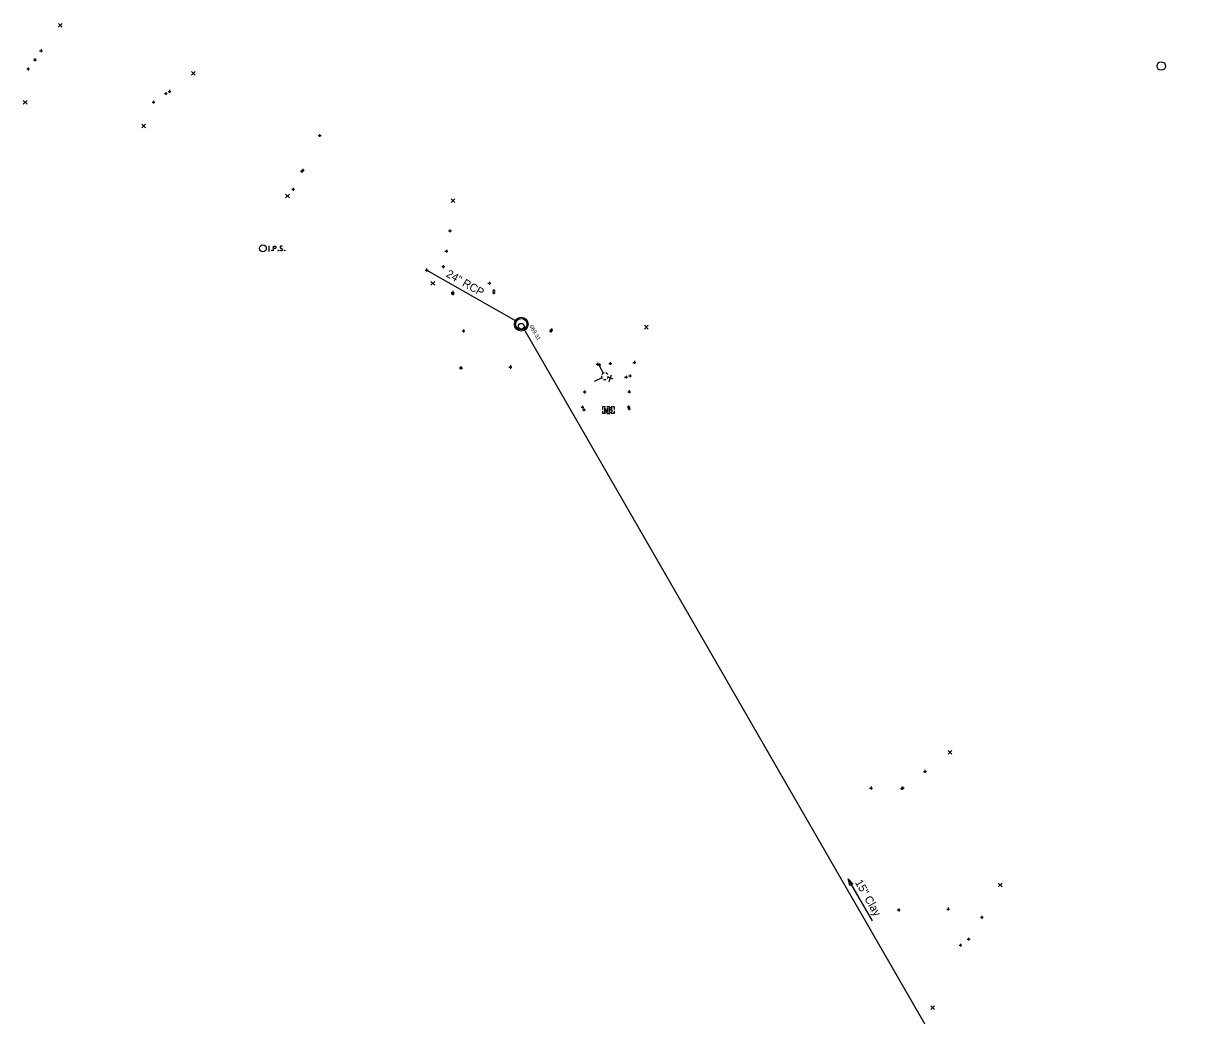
# Model space of a CAD drawing. Extents: x 2188719 to 2189819, y 654569 to 659504.
# Drawn here: x 2189134.5 to 2189542.6, y 658968.9 to 659316 of the extents above; entities that cross this region are included whole.
import ezdxf

# ---------------------------------------------------------------- set-up
doc = ezdxf.new("R2010")
doc.units = 0
for name, color, linetype in [('DR_X_Cells', 7, 'Continuous'), ('DR_X_Elev_Flow', 7, 'Continuous'), ('DR_X_Storm_Sewer', 7, 'Continuous'), ('DR_X_Text', 7, 'Continuous'), ('GK_Drainage_Nodes', 7, 'Continuous'), ('RD_X_Cells', 7, 'Continuous'), ('SC_Scratch1', 7, 'Continuous'), ('SV_P_Mon_Cells_Set', 7, 'Continuous'), ('SV_X_Random_Point', 7, 'Continuous'), ('SV_X_Shot_Marker', 7, 'Continuous'), ('UT_X_Water_Cells', 7, 'Continuous')]:
    doc.layers.add(name, color=color, linetype=linetype)

msp = doc.modelspace()

# ---------------------------------------------------------------- linework, layer by layer
at = {"layer": 'DR_X_Cells'}
for centre, radius in [((2189308.74, 659210.8), 2.42), ((2189308.74, 659210.8), 2), ((2189308.74, 659210.05), 1)]:
    msp.add_circle(centre, radius, dxfattribs=at)
at = {"layer": 'DR_X_Elev_Flow'}
for p, q in [((2189275.13, 659229.7), (2189276.13, 659229.7)), ((2189275.63, 659230.2), (2189275.63, 659229.2)), ((2189275.63, 659229.7), (2189275.63, 659229.7))]:
    msp.add_line(p, q, dxfattribs=at)
at = {"layer": 'DR_X_Storm_Sewer'}
for p, q in [((2189306.96, 659211.82), (2189275.63, 659229.7)), ((2189542.62, 658805.63), (2189309.74, 659209.07))]:
    msp.add_line(p, q, dxfattribs=at)
at = {"layer": 'DR_X_Text'}
msp.add_line((2189431.6, 659002.02), (2189423.08, 659016.79), dxfattribs=at)
msp.add_lwpolyline([(2189423.08, 659016.79), (2189424.8, 659015.01), (2189423.76, 659014.41)], close=True, dxfattribs=at)
at = {"layer": 'GK_Drainage_Nodes'}
for p, q in [((2189308.74, 659212.8), (2189308.74, 659212.8)), ((2189308.74, 659210.8), (2189308.74, 659210.8)), ((2189308.74, 659210.8), (2189308.74, 659210.8)), ((2189308.74, 659210.05), (2189308.74, 659210.05)), ((2189308.74, 659208.8), (2189308.74, 659208.8))]:
    msp.add_line(p, q, dxfattribs=at)
msp.add_circle((2189308.74, 659210.8), 2, dxfattribs=at)
at = {"layer": 'RD_X_Cells'}
for p, q in [((2189338.72, 659181.96), (2189339.72, 659181.96)), ((2189338.72, 659179.52), (2189339.72, 659179.52)), ((2189339.23, 659180.74), (2189339.23, 659180.74))]:
    msp.add_line(p, q, dxfattribs=at)
for points in [[(2189337.23, 659180.99), (2189337.23, 659181.96), (2189338.2, 659181.96)], [(2189338.2, 659179.52), (2189337.23, 659179.52), (2189337.23, 659180.49)], [(2189337.93, 659179.94), (2189337.93, 659181.54), (2189338.51, 659179.94), (2189339.07, 659181.54), (2189339.07, 659179.94)], [(2189340.25, 659180.81), (2189340.31, 659180.87), (2189340.35, 659180.91), (2189340.38, 659180.94), (2189340.39, 659180.97), (2189340.41, 659181.02), (2189340.43, 659181.06), (2189340.45, 659181.15), (2189340.45, 659181.18), (2189340.45, 659181.23), (2189340.44, 659181.31), (2189340.41, 659181.37), (2189340.38, 659181.42), (2189340.31, 659181.47), (2189340.26, 659181.5), (2189340.24, 659181.51), (2189340.17, 659181.54), (2189339.56, 659181.54), (2189339.56, 659179.94), (2189340.25, 659179.94), (2189340.34, 659179.99), (2189340.41, 659180.05), (2189340.48, 659180.15), (2189340.51, 659180.26), (2189340.53, 659180.38), (2189340.53, 659180.45), (2189340.5, 659180.53), (2189340.45, 659180.64), (2189340.39, 659180.72), (2189340.25, 659180.81), (2189339.56, 659180.81)], [(2189340.23, 659181.96), (2189341.23, 659181.96), (2189341.23, 659180.99)], [(2189341.23, 659180.49), (2189341.23, 659179.52), (2189340.23, 659179.52)]]:
    msp.add_lwpolyline(points, dxfattribs=at)
at = {"layer": 'SV_P_Mon_Cells_Set'}
for points in [[(2189220.34, 659238.08), (2189220.69, 659238.08)], [(2189220.34, 659236.48), (2189220.69, 659236.48)], [(2189220.51, 659236.48), (2189220.51, 659238.08)], [(2189221.47, 659236.69), (2189221.53, 659236.69), (2189221.56, 659236.67), (2189221.59, 659236.62), (2189221.59, 659236.55), (2189221.56, 659236.5), (2189221.53, 659236.48), (2189221.47, 659236.48), (2189221.44, 659236.5), (2189221.41, 659236.55), (2189221.41, 659236.62), (2189221.44, 659236.67), (2189221.47, 659236.69)], [(2189222.08, 659236.48), (2189222.08, 659238.08), (2189222.61, 659238.08), (2189222.66, 659238.06), (2189222.74, 659238.04), (2189222.77, 659238.01), (2189222.81, 659237.99), (2189222.85, 659237.93), (2189222.88, 659237.86), (2189222.91, 659237.76), (2189222.91, 659237.61), (2189222.89, 659237.56), (2189222.87, 659237.49), (2189222.83, 659237.4), (2189222.78, 659237.36), (2189222.75, 659237.33), (2189222.7, 659237.31), (2189222.61, 659237.3), (2189222.08, 659237.3)], [(2189223.72, 659236.69), (2189223.78, 659236.69), (2189223.81, 659236.67), (2189223.84, 659236.62), (2189223.84, 659236.55), (2189223.81, 659236.5), (2189223.78, 659236.48), (2189223.72, 659236.48), (2189223.69, 659236.5), (2189223.65, 659236.55), (2189223.65, 659236.62), (2189223.69, 659236.67), (2189223.72, 659236.69)], [(2189225.09, 659237.96), (2189225.07, 659237.99), (2189225.03, 659238.01), (2189224.93, 659238.05), (2189224.81, 659238.08), (2189224.72, 659238.08), (2189224.69, 659238.08), (2189224.55, 659238.04), (2189224.43, 659237.96), (2189224.35, 659237.86), (2189224.33, 659237.76), (2189224.33, 659237.69), (2189224.35, 659237.59), (2189224.44, 659237.5), (2189225.04, 659237.12), (2189225.1, 659237.07), (2189225.12, 659237.02), (2189225.14, 659236.94), (2189225.14, 659236.87), (2189225.13, 659236.79), (2189225.12, 659236.74), (2189225.1, 659236.68), (2189225.08, 659236.63), (2189225.05, 659236.59), (2189225.02, 659236.55), (2189224.99, 659236.53), (2189224.94, 659236.5), (2189224.91, 659236.49), (2189224.81, 659236.48), (2189224.66, 659236.48), (2189224.56, 659236.5), (2189224.42, 659236.59), (2189224.33, 659236.67)], [(2189225.9, 659236.69), (2189225.96, 659236.69), (2189225.99, 659236.67), (2189226.02, 659236.62), (2189226.02, 659236.55), (2189225.99, 659236.5), (2189225.96, 659236.48), (2189225.9, 659236.48), (2189225.87, 659236.5), (2189225.84, 659236.55), (2189225.84, 659236.62), (2189225.87, 659236.67), (2189225.9, 659236.69)]]:
    msp.add_lwpolyline(points, dxfattribs=at)
for centre, radius in [((2189532.7, 659301.08), 1.5), ((2189218.32, 659237.28), 1.2)]:
    msp.add_circle(centre, radius, dxfattribs=at)
at = {"layer": 'SV_X_Random_Point'}
for p, q in [((2189146.81, 659314.68), (2189148.14, 659316.01)), ((2189146.81, 659316.01), (2189148.14, 659314.68)), ((2189193.32, 659297.83), (2189194.65, 659299.16)), ((2189193.32, 659299.16), (2189194.65, 659297.83)), ((2189134.5, 659287.72), (2189135.84, 659289.05)), ((2189134.5, 659289.05), (2189135.84, 659287.72)), ((2189175.98, 659279.41), (2189177.31, 659280.74)), ((2189175.98, 659280.74), (2189177.31, 659279.41)), ((2189226.29, 659254.96), (2189227.62, 659256.3)), ((2189226.29, 659256.3), (2189227.62, 659254.96)), ((2189284.17, 659253.32), (2189285.5, 659254.66)), ((2189284.17, 659254.66), (2189285.5, 659253.32)), ((2189277.14, 659224.42), (2189278.47, 659225.76)), ((2189277.14, 659225.76), (2189278.47, 659224.42)), ((2189351.82, 659209.08), (2189353.15, 659210.41)), ((2189351.82, 659210.41), (2189353.15, 659209.08)), ((2189458.08, 659060.34), (2189459.41, 659061.68)), ((2189458.08, 659061.68), (2189459.41, 659060.34)), ((2189475.67, 659013.96), (2189477.01, 659015.3)), ((2189475.67, 659015.3), (2189477.01, 659013.96)), ((2189452.02, 658971.02), (2189453.36, 658972.35)), ((2189452.02, 658972.35), (2189453.36, 658971.02))]:
    msp.add_line(p, q, dxfattribs=at)
at = {"layer": 'SV_X_Shot_Marker'}
for p, q in [((2189140.21, 659306.44), (2189141.21, 659306.44)), ((2189140.71, 659306.94), (2189140.71, 659305.94)), ((2189140.71, 659306.44), (2189140.71, 659306.44)), ((2189138.07, 659303.28), (2189139.07, 659303.28)), ((2189138.57, 659303.78), (2189138.57, 659302.78)), ((2189138.57, 659303.28), (2189138.57, 659303.28)), ((2189135.68, 659300.07), (2189136.68, 659300.07)), ((2189136.18, 659300.57), (2189136.18, 659299.57)), ((2189136.18, 659300.07), (2189136.18, 659300.07)), ((2189183.86, 659291.49), (2189184.86, 659291.49)), ((2189184.36, 659291.99), (2189184.36, 659290.99)), ((2189184.36, 659291.49), (2189184.36, 659291.49)), ((2189185.15, 659292.21), (2189186.15, 659292.21)), ((2189185.65, 659292.71), (2189185.65, 659291.71)), ((2189185.65, 659292.21), (2189185.65, 659292.21)), ((2189179.55, 659288.45), (2189180.55, 659288.45)), ((2189180.05, 659288.95), (2189180.05, 659287.95)), ((2189180.05, 659288.45), (2189180.05, 659288.45)), ((2189237.67, 659276.78), (2189238.67, 659276.78)), ((2189238.17, 659277.28), (2189238.17, 659276.28)), ((2189238.17, 659276.78), (2189238.17, 659276.78)), ((2189231.83, 659264.65), (2189232.83, 659264.65)), ((2189231.98, 659264.75), (2189231.98, 659263.75)), ((2189232.33, 659265.15), (2189232.33, 659264.15)), ((2189232.33, 659264.65), (2189232.33, 659264.65)), ((2189231.48, 659264.25), (2189232.48, 659264.25)), ((2189231.98, 659264.25), (2189231.98, 659264.25)), ((2189228.42, 659257.95), (2189229.42, 659257.95)), ((2189228.92, 659258.45), (2189228.92, 659257.45)), ((2189228.92, 659257.95), (2189228.92, 659257.95)), ((2189283.28, 659243.43), (2189284.28, 659243.43)), ((2189283.78, 659243.93), (2189283.78, 659242.93)), ((2189283.78, 659243.43), (2189283.78, 659243.43)), ((2189282.04, 659236.31), (2189283.04, 659236.31)), ((2189282.54, 659236.81), (2189282.54, 659235.81)), ((2189282.54, 659236.31), (2189282.54, 659236.31)), ((2189280.94, 659230.9), (2189281.94, 659230.9)), ((2189281.44, 659231.4), (2189281.44, 659230.4)), ((2189281.44, 659230.9), (2189281.44, 659230.9)), ((2189297.08, 659225.07), (2189298.08, 659225.07)), ((2189297.58, 659225.57), (2189297.58, 659224.57)), ((2189297.58, 659225.07), (2189297.58, 659225.07)), ((2189284.25, 659221.9), (2189285.25, 659221.9)), ((2189284.25, 659221.45), (2189285.25, 659221.45)), ((2189284.75, 659222.4), (2189284.75, 659221.4)), ((2189284.75, 659221.95), (2189284.75, 659220.95)), ((2189284.75, 659221.9), (2189284.75, 659221.9)), ((2189284.75, 659221.45), (2189284.75, 659221.45)), ((2189298.64, 659221.79), (2189299.64, 659221.79)), ((2189298.66, 659222.48), (2189299.66, 659222.48)), ((2189299.14, 659222.29), (2189299.14, 659221.29)), ((2189299.14, 659221.79), (2189299.14, 659221.79)), ((2189299.16, 659222.98), (2189299.16, 659221.98)), ((2189299.16, 659222.48), (2189299.16, 659222.48)), ((2189288.02, 659208.42), (2189289.02, 659208.42)), ((2189288.52, 659208.92), (2189288.52, 659207.92)), ((2189288.52, 659208.42), (2189288.52, 659208.42)), ((2189309.58, 659209.44), (2189310.58, 659209.44)), ((2189310.08, 659209.94), (2189310.08, 659208.94)), ((2189310.08, 659209.44), (2189310.08, 659209.44)), ((2189318.61, 659208.35), (2189319.61, 659208.35)), ((2189318.77, 659208.8), (2189319.77, 659208.8)), ((2189319.11, 659208.85), (2189319.11, 659207.85)), ((2189319.11, 659208.35), (2189319.11, 659208.35)), ((2189319.27, 659209.3), (2189319.27, 659208.3)), ((2189319.27, 659208.8), (2189319.27, 659208.8)), ((2189287.11, 659195.63), (2189288.11, 659195.63)), ((2189287.12, 659195.41), (2189288.12, 659195.41)), ((2189287.61, 659196.13), (2189287.61, 659195.13)), ((2189287.61, 659195.63), (2189287.61, 659195.63)), ((2189287.62, 659195.91), (2189287.62, 659194.91)), ((2189287.62, 659195.41), (2189287.62, 659195.41)), ((2189304.44, 659195.69), (2189305.44, 659195.69)), ((2189304.45, 659195.89), (2189305.45, 659195.89)), ((2189304.94, 659196.19), (2189304.94, 659195.19)), ((2189304.94, 659195.69), (2189304.94, 659195.69)), ((2189304.95, 659196.39), (2189304.95, 659195.39)), ((2189304.95, 659195.89), (2189304.95, 659195.89)), ((2189334.94, 659196.8), (2189335.94, 659196.8)), ((2189335.44, 659197.3), (2189335.44, 659196.3)), ((2189335.44, 659196.8), (2189335.44, 659196.8)), ((2189335.57, 659196.58), (2189336.57, 659196.58)), ((2189336.07, 659197.08), (2189336.07, 659196.08)), ((2189336.07, 659196.58), (2189336.07, 659196.58)), ((2189339.39, 659197.04), (2189340.39, 659197.04)), ((2189339.89, 659197.54), (2189339.89, 659196.54)), ((2189339.89, 659197.04), (2189339.89, 659197.04)), ((2189347.82, 659197.41), (2189348.82, 659197.41)), ((2189348.32, 659197.91), (2189348.32, 659196.91)), ((2189348.32, 659197.41), (2189348.32, 659197.41)), ((2189344.89, 659192.26), (2189345.89, 659192.26)), ((2189345.39, 659192.76), (2189345.39, 659191.76)), ((2189345.39, 659192.26), (2189345.39, 659192.26)), ((2189346.31, 659192.69), (2189347.31, 659192.69)), ((2189346.31, 659192.69), (2189347.31, 659192.69)), ((2189346.81, 659193.19), (2189346.81, 659192.19)), ((2189346.81, 659193.19), (2189346.81, 659192.19)), ((2189346.81, 659192.69), (2189346.81, 659192.69)), ((2189346.81, 659192.69), (2189346.81, 659192.69)), ((2189330.4, 659187.06), (2189331.4, 659187.06)), ((2189330.9, 659187.56), (2189330.9, 659186.56)), ((2189330.9, 659187.06), (2189330.9, 659187.06)), ((2189346.05, 659187.17), (2189347.05, 659187.17)), ((2189346.55, 659187.67), (2189346.55, 659186.67)), ((2189346.55, 659187.17), (2189346.55, 659187.17)), ((2189329.67, 659181.73), (2189330.67, 659181.73)), ((2189330.16, 659180.81), (2189331.16, 659180.81)), ((2189330.17, 659182.23), (2189330.17, 659181.23)), ((2189330.17, 659181.73), (2189330.17, 659181.73)), ((2189330.66, 659181.31), (2189330.66, 659180.31)), ((2189330.66, 659180.81), (2189330.66, 659180.81)), ((2189345.8, 659181.88), (2189346.8, 659181.88)), ((2189346, 659181.17), (2189347, 659181.17)), ((2189346.3, 659182.38), (2189346.3, 659181.38)), ((2189346.3, 659181.88), (2189346.3, 659181.88)), ((2189346.5, 659181.67), (2189346.5, 659180.67)), ((2189346.5, 659181.17), (2189346.5, 659181.17)), ((2189449.5, 659054.34), (2189450.5, 659054.34)), ((2189450, 659054.84), (2189450, 659053.84)), ((2189450, 659054.34), (2189450, 659054.34)), ((2189430.62, 659048.51), (2189431.62, 659048.51)), ((2189431.12, 659049.01), (2189431.12, 659048.01)), ((2189431.12, 659048.51), (2189431.12, 659048.51)), ((2189441.42, 659048.41), (2189442.42, 659048.41)), ((2189441.62, 659048.47), (2189442.62, 659048.47)), ((2189441.68, 659048.56), (2189442.68, 659048.56)), ((2189441.92, 659048.91), (2189441.92, 659047.91)), ((2189441.92, 659048.41), (2189441.92, 659048.41)), ((2189442.12, 659048.97), (2189442.12, 659047.97)), ((2189442.12, 659048.47), (2189442.12, 659048.47)), ((2189442.18, 659049.06), (2189442.18, 659048.06)), ((2189442.18, 659048.56), (2189442.18, 659048.56)), ((2189440.31, 659005.89), (2189441.31, 659005.89)), ((2189440.81, 659006.39), (2189440.81, 659005.39)), ((2189440.81, 659005.89), (2189440.81, 659005.89)), ((2189457.6, 659006.18), (2189458.6, 659006.18)), ((2189457.62, 659006.14), (2189458.62, 659006.14)), ((2189458.1, 659006.68), (2189458.1, 659005.68)), ((2189458.1, 659006.18), (2189458.1, 659006.18)), ((2189458.12, 659006.64), (2189458.12, 659005.64)), ((2189458.12, 659006.14), (2189458.12, 659006.14)), ((2189469.4, 659003.32), (2189470.4, 659003.32)), ((2189469.9, 659003.82), (2189469.9, 659002.82)), ((2189469.9, 659003.32), (2189469.9, 659003.32)), ((2189464.77, 658995.68), (2189465.77, 658995.68)), ((2189465.27, 658996.18), (2189465.27, 658995.18)), ((2189465.27, 658995.68), (2189465.27, 658995.68)), ((2189461.94, 658993.57), (2189462.94, 658993.57)), ((2189462.44, 658994.07), (2189462.44, 658993.07)), ((2189462.44, 658993.57), (2189462.44, 658993.57))]:
    msp.add_line(p, q, dxfattribs=at)
at = {"layer": 'UT_X_Water_Cells'}
for p, q in [((2189337.44, 659193.65), (2189336.14, 659196.28)), ((2189336.9, 659192.05), (2189334.27, 659190.74)), ((2189337.98, 659192.58), (2189337.98, 659192.58)), ((2189337.98, 659192.58), (2189337.98, 659192.58)), ((2189339.12, 659192.19), (2189340.75, 659191.64)), ((2189339.55, 659190.78), (2189340.31, 659193.06))]:
    msp.add_line(p, q, dxfattribs=at)
for start, end in [(175.2078, 221.2935), (103.2626, 147.2318), (247.4003, 291.3727), (31.4049, 75.4468), (319.5233, 3.4218)]:
    msp.add_arc((2189337.98, 659192.58), 1.2, start, end, dxfattribs=at)

# ---------------------------------------------------------------- texts
at = {"layer": 'DR_X_Text'}
for s, rotation, p in [('24" RCP', 330.2779, (2189282.18, 659227.58)), ('15" Clay', 299.9954, (2189425.43, 659015.51))]:
    msp.add_text(s, height=2.8, rotation=rotation, dxfattribs=at).set_placement(p)
at = {"layer": 'SC_Scratch1'}
msp.add_text('669.31', height=1.4, rotation=299.9954, dxfattribs=at).set_placement((2189311.5, 659210.08))

doc.saveas('drawing.dxf')
